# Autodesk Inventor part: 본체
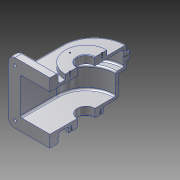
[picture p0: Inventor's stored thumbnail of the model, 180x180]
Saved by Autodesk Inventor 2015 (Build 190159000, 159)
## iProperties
Created: 2017-11
Part Number: 본체
Material: 알루미늄 6061
Document SubType Name: Modeling
Designer: 2-PC06
Density: 2.7 g/cm^3
Appearance: 알루미늄 - 평지
Mass: 1100.61 g
Surface Area: 1209.59 cm^2
Volume: 407.632 cm^3
Author: 2-PC06
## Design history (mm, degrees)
sketch "스케치1"
  geometry: L1 (-75, 55)-(75, 55); L2 (75, 55)-(75, -55); L3 (75, -55)-(-75, -55); L4 (-75, -55)-(-75, 55); L5 (-75, 55)-(75, -55); L6 (75, 55)-(-75, -55); 1 further point
  constraints: 12 end point, 2 midpoint, 2 parallel, 1 horizontal, 1 perpendicular
  dimensions: "d0" = 110 distance of L1.end L2.end; "d1" = 150 distance of L2.end L3.end
extrude "돌출1" new body sketch "스케치1" distance "d2" = 15; taper "d3" = 0 deg
sketch "스케치2"
  geometry: L1 (75, 0)-(-75, 0) reference; L2 (0, 80)-(0, 0); L3 (-58, 80)-(-58, 15); L4 (-75, 15)-(75, 15) reference; L5 (58, 80)-(58, 15); A1 r 58 centre (0, 80) between (58, 80) and (-58, 80)
  constraints: 6 end point, 2 perpendicular, 2 point on circle, 2 point on line, 2 tangent, 1 centre point, 1 vertical
  dimensions: "d4" = 116 diameter of A1; "d5" = 80 distance from line of L1 L2.start
extrude "돌출2" join sketch "스케치2" distance "d7" = 38; taper "d8" = 0 deg
sketch "스케치3"
  geometry: L1 (75, 0)-(-75, 0) reference; L2 (0, 65)-(0, 0); L3 (58, 80)-(58, 15) reference; L4 (58, 65)-(58, 15); L5 (58, 15)-(-58, 15); L6 (-75, 15)-(75, 15) reference; L7 (-58, 15)-(-58, 65); L8 (-58, 15)-(-58, 80) reference; A1 r 58 centre (0, 65) between (58, 65) and (-58, 65)
  constraints: 8 end point, 2 collinear, 2 point on circle, 2 point on line, 1 centre point, 1 perpendicular
  dimensions: "d10" = 65 distance from line of L1 L2.start; "d11" = 58 radius of A1
extrude "돌출3" join sketch "스케치3" distance "d12" = 38; taper "d13" = 0 deg
sketch "스케치4"
  geometry: C1 r 31 at (0, 65); A1 r 58 centre (0, 65) between (58, 65) and (-58, 65) reference; 1 further point
  constraints: 1 centre point, 1 concentric
  dimensions: "d14" = 62 diameter of C1
extrude "돌출4" join sketch "스케치4" distance "d15" = 10; taper "d16" = 0 deg
sketch "스케치5"
  geometry: C1 r 37.5 at (0, 65); C2 r 31 at (0, 65) reference; 1 further point
  constraints: 1 centre point, 1 concentric
  dimensions: "d17" = 75 diameter of C1
extrude "돌출5" join sketch "스케치5" distance "d18" = 9; taper "d19" = 0 deg
feature "쉘1" dims "d23" = 5
sketch "스케치7"
  geometry: C1 r 16 at (0, 0); C2 r 37.5 at (0, 0) reference; 1 further point
  constraints: 1 centre point, 1 concentric
  dimensions: "d24" = 32 diameter of C1
extrude "돌출7" cut sketch "스케치7" stored distance "d25" = 15; taper "d26" = 0 deg
sketch "스케치8"
  geometry: L1 (17, -83)-(123, -83); L2 (123, -83)-(123, -17); L3 (123, -17)-(17, -17); L4 (17, -17)-(17, -83); L5 (17, -83)-(123, -17); L6 (123, -83)-(17, -17); L7 (0, -100)-(140, -100); L8 (140, -100)-(140, 0); L9 (140, 0)-(0, 0); L10 (0, 0)-(0, -100); L11 (0, -100)-(140, 0); L12 (140, -100)-(0, 0); 1 further point
  constraints: 24 end point, 4 midpoint, 4 parallel, 2 horizontal, 2 perpendicular
extrude "돌출8" join sketch "스케치8" distance "d27" = 10; taper "d28" = 0 deg
fillet "모깎기1" dims "d29" = 12
node "작업 평면1"
sketch "스케치9"
  geometry: L1 (-75, -43)-(-75, 43) reference; L2 (58, 38)-(-58, 38) reference; C1 r 6 at (0, 19); 1 further point
  constraints: 1 centre point
  dimensions: "d31" = 12 diameter of C1; "d32" = 75 distance from line of L1 C1.centre; "d33" = 19 distance from line of L2 C1.centre
extrude "돌출9" join sketch "스케치9" stored distance "d34" = 15; taper "d35" = 0 deg
sketch "스케치10"
  geometry: C1 r 6 at (-63, -43); A1 r 12 centre (-63, -43) between (-75, -43) and (-63, -55) reference; 1 further point
  constraints: 1 centre point, 1 concentric
  dimensions: "d36" = 12 diameter of C1
extrude "돌출10" cut sketch "스케치10" distance "d37" = 5; taper "d38" = 0 deg
sketch "스케치11"
  geometry: C1 r 2.5 at (0, 0); C2 r 6 at (0, 0) reference; 1 further point
  constraints: 1 centre point, 1 concentric
  dimensions: "d39" = 5 diameter of C1
extrude "돌출11" cut sketch "스케치11" stored distance "d40" = 5; taper "d41" = 0 deg
fillet "모깎기2" dims "d42" = 3
chamfer "모따기1" distance "d43" = 1; stored, may be unused: second distance "d44" = 2, angle "d45" = 45 deg
fillet "모깎기3" dims "d46" = 3
fillet "모깎기4" dims "d47" = 3
sketch "스케치16"
  geometry: C1 r 16 at (0, 0) reference; C2 r 32.5 at (0, 0) reference; 1 further point
extrude "돌출12" join sketch "스케치16" stored distance "d82" = 5; taper "d83" = 0 deg
sketch "스케치12"
  geometry: L1 (0, 29)-(0, 0); C1 r 26 at (0, 0) reference; 1 further point
  constraints: 2 end point, 1 vertical
  dimensions: "d48" = 29 distance of L1.start L1.end
hole "구멍1" sketch "스케치12" at (0, 29) diameter "d49" = 2.459; stored, may be unused: countersink angle "d53" = 90 deg, drill point angle "d55" = 118 deg; dims "d50" = 6, "d51" = 12, "d52" = 5, "d54" = 8.8
sketch "스케치13" dims "d59" = 52
  geometry: C1 r 31 at (0, 0) reference; 3 further points
  constraints: 2 vertical alignment, 3 other
hole "구멍2" sketch "스케치13" at (0, 26) diameter "d60" = 2.459; stored, may be unused: countersink angle "d64" = 90 deg, drill point angle "d66" = 118 deg; dims "d61" = 6, "d62" = 12, "d63" = 5, "d65" = 8.8
sketch "스케치17"
  geometry: C1 r 16 at (0, -26) reference; C2 r 26 at (0, -26) reference; 1 further point
extrude "돌출13" join sketch "스케치17" stored distance "d84" = 5; taper "d85" = 0 deg
sketch "스케치14"
  geometry: L1 (6, 0)-(-6, 0); L2 (0, -6)-(0, 6); A1 r 6 centre (0, 0) between (6, 0) and (-6, 0) reference; 2 further points
  constraints: 4 end point, 4 point on circle, 1 coincident, 1 horizontal, 1 vertical
hole "구멍3" sketch "스케치14" at (0, 0) diameter "d70" = 4.134; stored, may be unused: countersink angle "d74" = 90 deg, drill point angle "d76" = 118 deg; dims "d71" = 10, "d72" = 12, "d73" = 5, "d75" = 14.2
sketch "스케치15"
  geometry: L1 (-24.246, -15.885)-(30.246, -15.885); L2 (30.246, -15.885)-(30.246, -34.115); L3 (30.246, -34.115)-(-24.246, -34.115); L4 (-24.246, -34.115)-(-24.246, -15.885); L5 (-24.246, -25)-(30.246, -25); L6 (3, -15.885)-(3, -34.115); L7 (-35, 15)-(-35, -47) reference; L8 (46, -65)-(-40, -65) reference; 1 further point
  constraints: 4 end point, 4 midpoint, 2 other
  dimensions: "d77" = 38 distance between parallel lines of L7 L6; "d78" = 40 distance between parallel lines of L8 L5
feature "엠보싱1" sketch "스케치15" dims "d79" = 0.5, "d80" = 0
fillet "모깎기5" dims "d81" = 3
node "솔리드1"
mirror "대칭1"
mirror "대칭2"
mirror "대칭3"
mirror "대칭4"
pattern_circular "원형 패턴1" dims angle "d57" = 360 deg
pattern_circular "원형 패턴2" dims angle "d68" = 360 deg
other parameters: "d6" = 38, "d9" = 116, "d30" = -144
